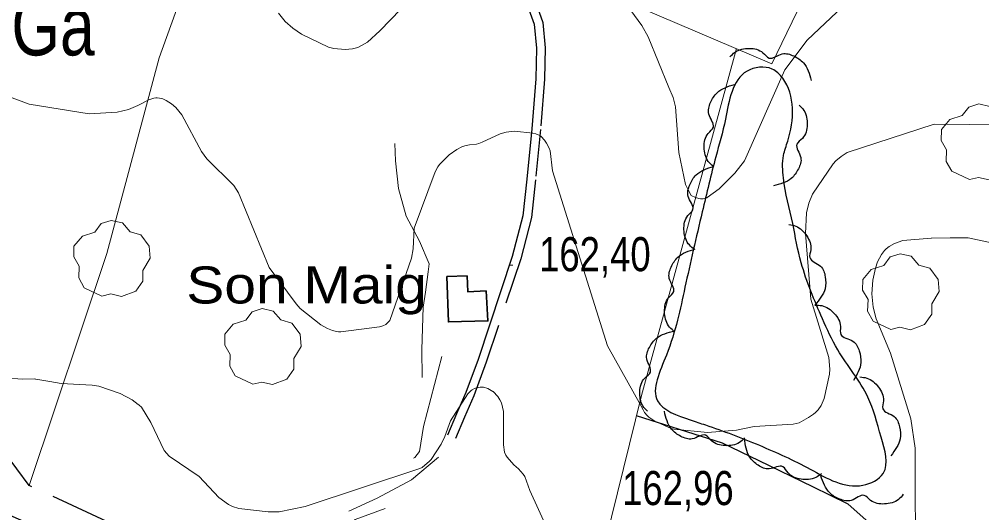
# Model space of a CAD drawing. Extents: x 483840 to 488445, y 4386047 to 4389027.
# Drawn here: x 484357.8 to 484604.8, y 4386593.6 to 4386720.2 of the extents above; entities that cross this region are included whole.
import ezdxf
from ezdxf.enums import TextEntityAlignment as Align

# ---------------------------------------------------------------- set-up
doc = ezdxf.new("R2010")
doc.units = 0
doc.header["$LTSCALE"] = 4
doc.linetypes.add('LONG_DASHED', pattern=[7.5, 6, -1.5])
doc.linetypes.add('MEDIUM_DASHED', pattern=[4.5, 3, -1.5])
for name, color, linetype, lineweight in [('25', 7, 'LONG_DASHED', 25), ('27', 7, 'Continuous', 25), ('29', 7, 'Continuous', 13), ('38', 7, 'Continuous', 25), ('47', 7, 'Continuous', 35), ('51', 7, 'Continuous', 13), ('7', 7, 'Continuous', 13), ('9', 7, 'Continuous', 13)]:
    doc.layers.add(name, color=color, linetype=linetype, lineweight=lineweight)
doc.layers.add('31', color=7, linetype='Continuous')
doc.layers.add('5', color=7, linetype='Continuous')

msp = doc.modelspace()

# ---------------------------------------------------------------- linework, layer by layer
at = {"layer": '25'}
for points in [[(484360.41, 4386600.63), (484354.02, 4386609.13), (484342.83, 4386622.33), (484338.08, 4386628.43), (484332.17, 4386636.95), (484328.3, 4386644.98), (484318.53, 4386649.68), (484308.26, 4386654.85)], [(484625.09, 4386565.41), (484619.55, 4386565.24), (484606.23, 4386564.53), (484601.69, 4386564.69), (484597.73, 4386565.92), (484588.84, 4386577.12), (484578.87, 4386588.38), (484570.49, 4386595.81), (484561.42, 4386600.29), (484547.69, 4386606.96), (484538.24, 4386611.5), (484516.24, 4386618.5)], [(484502.07, 4386561.29), (484498.4, 4386548.69), (484496.9, 4386545.14), (484493.33, 4386545.09), (484491.54, 4386545.96), (484488.97, 4386547.31), (484486.16, 4386546.59), (484479.53, 4386549.16), (484472.38, 4386552.84), (484468.67, 4386554.43), (484462.27, 4386557.73), (484455.18, 4386561.19), (484448, 4386562.42), (484443.71, 4386561.42), (484440.31, 4386560.77), (484431.57, 4386564.01), (484408.49, 4386578.31), (484399.65, 4386582.16), (484388.31, 4386587.7), (484360.41, 4386600.63)]]:
    msp.add_lwpolyline(points, dxfattribs=at)
at = {"layer": '27'}
for points in [[(484540.19, 4386710.56), (484541.48, 4386711.78), (484545.15, 4386712.74), (484548.66, 4386711.61), (484550.21, 4386710.26), (484553.6, 4386711.33), (484556.53, 4386710.79), (484559.01, 4386709.06), (484561.03, 4386704.53)], [(484556.32, 4386667.82), (484558.47, 4386657.74), (484563.92, 4386643.39), (484567.83, 4386635.44), (484575.57, 4386623.28), (484578.97, 4386613.01), (484579.51, 4386603.72), (484574.31, 4386600.68), (484560.8, 4386604.79), (484547.72, 4386610.93), (484533.87, 4386616.16), (484529.98, 4386617.43), (484521.57, 4386622.34), (484523.87, 4386634.06), (484528.64, 4386651.45), (484533.07, 4386670.79), (484536.55, 4386684.93), (484539.03, 4386694.61), (484544.56, 4386706.89), (484551.02, 4386707.43), (484553.72, 4386705.12), (484555.02, 4386688.98), (484553.92, 4386685.29), (484553.91, 4386679.51), (484556.32, 4386667.82)], [(484535.89, 4386682.49), (484534.63, 4386683.75), (484533.57, 4386687.39), (484534.61, 4386690.94), (484535.92, 4386692.52), (484534.75, 4386695.88), (484535.21, 4386698.83), (484536.87, 4386701.35), (484541.34, 4386703.5)], [(484557.95, 4386698.16), (484559.14, 4386696.84), (484559.99, 4386693.15), (484558.77, 4386689.66), (484557.37, 4386688.16), (484558.35, 4386684.74), (484557.73, 4386681.82), (484555.92, 4386679.39), (484551.34, 4386677.5)], [(484109.46, 4386593.06), (484150.94, 4386626.49), (484199.73, 4386650.7), (484203.95, 4386655.31), (484208.18, 4386661.85), (484210.1, 4386669.53), (484207.03, 4386691.82), (484208.56, 4386694.9), (484211.64, 4386696.82), (484215.48, 4386696.43), (484273.86, 4386668), (484283.08, 4386663), (484285.77, 4386658), (484291.92, 4386647.24), (484300.75, 4386636.1), (484310.35, 4386633.02), (484326.87, 4386627.64), (484334.94, 4386616.12), (484338.78, 4386603.82), (484350.3, 4386595.36), (484426.74, 4386553.47), (484429.82, 4386547.71), (484429.82, 4386545.79), (484429.82, 4386540.02), (484422.52, 4386535.03), (484386.41, 4386496.98), (484386.03, 4386493.91), (484387.56, 4386490.45), (484397.55, 4386477), (484431.35, 4386465.85), (484447.87, 4386459.7), (484460.55, 4386449.71), (484465.92, 4386445.87)], [(484530.77, 4386661.41), (484529.5, 4386662.64), (484528.39, 4386666.27), (484529.38, 4386669.83), (484530.66, 4386671.43), (484529.45, 4386674.77), (484529.87, 4386677.73), (484531.5, 4386680.27), (484535.95, 4386682.48)], [(484555.32, 4386667.55), (484557.05, 4386667.16), (484559.89, 4386664.65), (484560.92, 4386661.11), (484560.66, 4386659.07), (484563.44, 4386656.86), (484564.63, 4386654.12), (484564.58, 4386651.1), (484561.95, 4386646.89)], [(484525.68, 4386640.32), (484524.43, 4386641.58), (484523.4, 4386645.23), (484524.45, 4386648.76), (484525.77, 4386650.34), (484524.62, 4386653.71), (484525.1, 4386656.65), (484526.78, 4386659.17), (484531.26, 4386661.29)], [(484561.96, 4386646.86), (484563.74, 4386646.76), (484566.95, 4386644.74), (484568.54, 4386641.41), (484568.62, 4386639.36), (484571.72, 4386637.63), (484573.34, 4386635.12), (484573.78, 4386632.13), (484571.87, 4386627.55)], [(484519.02, 4386619.67), (484517.86, 4386621.01), (484517.06, 4386624.72), (484518.34, 4386628.18), (484519.76, 4386629.66), (484518.84, 4386633.1), (484519.5, 4386636.01), (484521.35, 4386638.41), (484525.96, 4386640.23)], [(484573.54, 4386628.45), (484575.29, 4386628.17), (484578.29, 4386625.85), (484579.54, 4386622.37), (484579.41, 4386620.32), (484582.32, 4386618.29), (484583.69, 4386615.63), (484583.82, 4386612.61), (484581.47, 4386608.25)], [(484543.94, 4386612.82), (484542.61, 4386611.65), (484538.9, 4386610.84), (484535.43, 4386612.1), (484533.94, 4386613.51), (484530.51, 4386612.57), (484527.6, 4386613.22), (484525.19, 4386615.05), (484523.35, 4386619.66)], [(484563.65, 4386603.66), (484562.19, 4386602.65), (484558.42, 4386602.23), (484555.11, 4386603.87), (484553.78, 4386605.43), (484550.27, 4386604.86), (484547.44, 4386605.82), (484545.25, 4386607.9), (484543.91, 4386612.68)], [(484584.65, 4386598.35), (484583.43, 4386597.05), (484579.83, 4386595.88), (484576.25, 4386596.8), (484574.63, 4386598.06), (484571.31, 4386596.79), (484568.34, 4386597.15), (484565.77, 4386598.73), (484563.48, 4386603.13)]]:
    msp.add_spline(points, degree=3, dxfattribs=at)
at = {"layer": '29'}
for points in [[(484601.62, 4386679.1), (484597.08, 4386681.22), (484595.67, 4386683.76), (484595.77, 4386686.74), (484594.4, 4386689.15), (484594.44, 4386691.9), (484596.6, 4386694.5), (484599.79, 4386695.5), (484601.44, 4386697.69), (484604.01, 4386698.52), (484606.87, 4386697.87), (484608.82, 4386695.6), (484611.63, 4386694.78), (484613.76, 4386691.93), (484614, 4386688.8), (484612.12, 4386685.65), (484612.12, 4386682.97), (484610.3, 4386680.36), (484606.68, 4386679.02), (484603.91, 4386679.65)], [(484379.06, 4386649.2), (484374.52, 4386651.32), (484373.11, 4386653.86), (484373.21, 4386656.84), (484371.84, 4386659.25), (484371.88, 4386662), (484374.04, 4386664.6), (484377.23, 4386665.6), (484378.88, 4386667.79), (484381.45, 4386668.62), (484384.31, 4386667.97), (484386.26, 4386665.7), (484389.07, 4386664.88), (484391.2, 4386662.03), (484391.44, 4386658.9), (484389.56, 4386655.75), (484389.56, 4386653.07), (484387.74, 4386650.46), (484384.12, 4386649.12), (484381.35, 4386649.75)], [(484581.45, 4386640.66), (484576.91, 4386642.78), (484575.5, 4386645.32), (484575.6, 4386648.3), (484574.23, 4386650.71), (484574.27, 4386653.46), (484576.43, 4386656.06), (484579.62, 4386657.06), (484581.27, 4386659.25), (484583.84, 4386660.08), (484586.7, 4386659.43), (484588.65, 4386657.16), (484591.46, 4386656.34), (484593.59, 4386653.49), (484593.83, 4386650.36), (484591.95, 4386647.21), (484591.95, 4386644.53), (484590.13, 4386641.92), (484586.51, 4386640.58), (484583.74, 4386641.21)], [(484417.78, 4386626.6), (484413.24, 4386628.72), (484411.83, 4386631.26), (484411.93, 4386634.24), (484410.56, 4386636.65), (484410.6, 4386639.4), (484412.76, 4386642), (484415.95, 4386643), (484417.6, 4386645.19), (484420.17, 4386646.02), (484423.03, 4386645.37), (484424.98, 4386643.1), (484427.79, 4386642.28), (484429.92, 4386639.43), (484430.16, 4386636.3), (484428.28, 4386633.15), (484428.28, 4386630.47), (484426.46, 4386627.86), (484422.84, 4386626.52), (484420.07, 4386627.15)]]:
    msp.add_lwpolyline(points, close=True, dxfattribs=at)
at = {"layer": '38'}
msp.add_lwpolyline([(484503.94, 4386804.39), (484500.14, 4386794.1), (484495.04, 4386779.48), (484492.44, 4386773.52), (484487.95, 4386764.75), (484483.27, 4386753.75), (484479.76, 4386743.29), (484479.64, 4386739.82), (484480.35, 4386735.84), (484482.04, 4386732.77), (484488.27, 4386723.67), (484489.97, 4386718.91), (484490.51, 4386712.77), (484490.38, 4386704.96), (484489.34, 4386692.14), (484488.04, 4386679.23), (484487.01, 4386669.77), (484484.32, 4386659.38), (484475.55, 4386632.97), (484472.4, 4386624.43), (484469.99, 4386619), (484467.68, 4386613.52)], dxfattribs=at)
at = {"layer": '38', "linetype": 'MEDIUM_DASHED'}
msp.add_lwpolyline([(484506.1, 4386803.76), (484502.25, 4386793.34), (484497.14, 4386778.66), (484494.47, 4386772.56), (484489.99, 4386763.8), (484485.37, 4386752.95), (484481.99, 4386742.89), (484481.89, 4386739.98), (484482.5, 4386736.6), (484483.96, 4386733.94), (484490.29, 4386724.69), (484492.18, 4386719.4), (484492.76, 4386712.85), (484492.63, 4386704.85), (484491.58, 4386691.94), (484490.27, 4386678.99), (484489.23, 4386669.37), (484486.49, 4386658.74), (484477.67, 4386632.22), (484474.48, 4386623.58), (484472.05, 4386618.11), (484469.75, 4386612.65)], dxfattribs=at)
at = {"layer": '47'}
msp.add_lwpolyline([(484467.51, 4386654.23), (484467.94, 4386642.56), (484478.07, 4386642.84), (484477.61, 4386650.54), (484472.95, 4386650.27), (484472.72, 4386654.36)], close=True, dxfattribs=at)
at = {"layer": '51'}
for points in [[(484426.66, 4386813.96), (484413.06, 4386763.95), (484393.76, 4386710.28), (484380.34, 4386660.15), (484360.41, 4386600.63)], [(484584.64, 4386778.48), (484550.96, 4386708.8), (484483.24, 4386737.68)], [(484541.9, 4386712.67), (484517.51, 4386623.68), (484502.07, 4386561.29)], [(484461.19, 4386628.31), (484461.14, 4386635.54), (484461.5, 4386646.36), (484462.08, 4386650.24), (484462.77, 4386655.4), (484463, 4386657.47), (484460.57, 4386663.28), (484457.09, 4386669.71), (484455.15, 4386676.76), (484454.4, 4386683.87), (484454.18, 4386688.31)], [(484466.25, 4386633.69), (484461.56, 4386615.74), (484460.56, 4386609.35), (484459.34, 4386607.79), (484458.97, 4386607.61)], [(484442.38, 4386594.04), (484449.67, 4386597.34), (484458.5, 4386602.06), (484465.42, 4386607.84)], [(484451.74, 4386594.71), (484444.01, 4386591.92), (484439.66, 4386587.8), (484434.99, 4386581.93), (484433.06, 4386579.22)]]:
    msp.add_lwpolyline(points, dxfattribs=at)
at = {"layer": '7'}
msp.add_line((484483.49, 4386657.16), (484484.49, 4386657.16), dxfattribs=at)
at = {"layer": '9'}
for points in [[(484455.72, 4386722.83), (484450.36, 4386717.24), (484447.18, 4386714.37), (484444.86, 4386713.03), (484444.72, 4386712.97), (484443.37, 4386712.65), (484441.49, 4386712.46), (484438.57, 4386712.68), (484437.2, 4386713.08), (484430.29, 4386716.41), (484428.03, 4386717.89), (484426.06, 4386719.63), (484424.4, 4386721.8)], [(484543.9, 4386683.87), (484541.4, 4386680.72), (484537.4, 4386676.72), (484534.35, 4386674.48), (484534.25, 4386674.39), (484534.1, 4386674.32), (484533.33, 4386674.18), (484532.61, 4386674.16), (484532.18, 4386674.24), (484531.37, 4386674.51), (484530.27, 4386675.04), (484529.26, 4386676.78), (484528.82, 4386677.81), (484527.08, 4386686.03), (484526.2, 4386697.77), (484525.62, 4386700.15), (484524.49, 4386702.73), (484519.22, 4386715.7), (484517.61, 4386718.65), (484514.73, 4386722.42)], [(484569.15, 4386723.49), (484560, 4386714.85), (484554.25, 4386707.23), (484543.9, 4386683.87)], [(484356.07, 4386700.09), (484360.43, 4386698.46), (484375.82, 4386695.94), (484382.94, 4386696.37), (484385.85, 4386697.03), (484388.27, 4386698.06), (484391.06, 4386699.54), (484391.85, 4386699.83), (484392.36, 4386699.97), (484392.9, 4386700.04), (484393.23, 4386700.04), (484393.87, 4386699.98), (484394.72, 4386699.76), (484395.54, 4386699.39), (484396.9, 4386698.51), (484397.98, 4386697.55), (484399.52, 4386695.68), (484404.62, 4386686.26), (484405.97, 4386684.44), (484412.86, 4386677.56), (484414.1, 4386675.69), (484421.93, 4386656.57), (484428.85, 4386647.2), (484429.93, 4386646), (484435.23, 4386641.86), (484436.92, 4386640.87), (484438.2, 4386640.35), (484438.92, 4386640.17), (484439.79, 4386640.05), (484440.35, 4386640.05), (484450.25, 4386641.29)], [(484450.25, 4386641.29), (484451.16, 4386641.53), (484451.89, 4386641.91), (484452.27, 4386642.22), (484452.9, 4386642.94), (484458.49, 4386658.9), (484458.92, 4386661.28), (484459.15, 4386666.61), (484464.53, 4386681.03), (484465.25, 4386682.32), (484465.68, 4386682.93), (484468.17, 4386685.4), (484470.07, 4386686.77), (484471.4, 4386687.47), (484472.19, 4386687.76), (484473.37, 4386688.02), (484475.14, 4386688.21), (484475.72, 4386688.36), (484476.58, 4386688.71), (484481.21, 4386690.85), (484482.79, 4386691.27), (484484.87, 4386691.49), (484489.57, 4386690.95), (484490.4, 4386690.78), (484491.01, 4386690.58), (484491.29, 4386690.44), (484491.73, 4386690.15), (484492.64, 4386689.19), (484493.15, 4386688.44), (484493.82, 4386687.11), (484494.03, 4386686.44), (484494.67, 4386681.31), (484508.78, 4386636.48), (484517.36, 4386621.17), (484517.9, 4386620), (484518.29, 4386619.37), (484518.93, 4386618.55), (484519.38, 4386618.14), (484520.91, 4386617.13), (484525.1, 4386615.27), (484525.76, 4386615.06), (484534.38, 4386614.25), (484541.86, 4386614.82), (484546.37, 4386615.75), (484556.41, 4386616.37), (484557.9, 4386616.73), (484560.35, 4386618.04), (484561.62, 4386618.9), (484562.16, 4386619.35), (484562.79, 4386620.02), (484563.57, 4386621.14), (484564.38, 4386622.94), (484565.72, 4386629.2), (484565.82, 4386630.42), (484565.56, 4386633.47), (484560.96, 4386648.4), (484559.56, 4386665.23), (484559.84, 4386670.52), (484560.41, 4386673.02), (484561.33, 4386675.35), (484566.67, 4386683.13), (484567.37, 4386683.93), (484568.69, 4386685.04), (484570.23, 4386686.01), (484592.56, 4386693.31), (484619.64, 4386693.04)], [(484587.78, 4386577.36), (484587.73, 4386610.21), (484586.55, 4386617.69), (484581.39, 4386634.53), (484577.66, 4386643.4), (484576.89, 4386646.39), (484576.62, 4386649.77), (484576.86, 4386653.28), (484577.49, 4386656.4), (484578.06, 4386658.01), (484579.06, 4386659.83), (484579.83, 4386660.86), (484580.28, 4386661.33), (484581.01, 4386661.9), (484582.36, 4386662.67), (484584.51, 4386663.44), (484591.84, 4386664.05), (484591.87, 4386664.06), (484596.69, 4386664.12), (484601.27, 4386664.14), (484612.06, 4386661.81)], [(484338.47, 4386629.29), (484358.75, 4386627.92), (484361.78, 4386627.95), (484362.01, 4386627.93), (484362.05, 4386627.9), (484362.06, 4386627.89), (484362.06, 4386627.91), (484362.06, 4386627.93), (484365.65, 4386627.27), (484368.6, 4386626.75), (484376.56, 4386626.33), (484378.23, 4386626.06), (484383.72, 4386624.23), (484386.8, 4386622.61), (484388.35, 4386621.43), (484388.51, 4386621.33), (484388.65, 4386621.23), (484389.17, 4386620.67), (484391.58, 4386616.8), (484395.05, 4386609.6), (484395.06, 4386609.59), (484396.29, 4386608.15), (484404.02, 4386602.9), (484409.08, 4386597.53), (484411.52, 4386595.75), (484412.57, 4386595.22), (484414.19, 4386594.69), (484421.73, 4386593.82), (484424.55, 4386593.89), (484431.2, 4386595.25), (484460.64, 4386604.95), (484461.23, 4386605.25), (484463.08, 4386606.83), (484463.54, 4386607.32)], [(484463.54, 4386607.32), (484466.06, 4386611.25), (484467.02, 4386613.2), (484468.52, 4386617.23), (484472.95, 4386624.14), (484473.43, 4386624.68), (484473.78, 4386625), (484474.05, 4386625.17), (484474.64, 4386625.46), (484475.44, 4386625.75), (484475.59, 4386625.78), (484476.12, 4386625.85), (484476.74, 4386625.84), (484476.97, 4386625.8), (484478.04, 4386625.51), (484479.38, 4386624.74), (484479.4, 4386624.73), (484480.59, 4386623.45), (484481.18, 4386622.57), (484481.53, 4386621.8), (484482.12, 4386619.6), (484482.12, 4386611.06), (484482.37, 4386609.15), (484482.7, 4386608.43), (484483.02, 4386607.84), (484484.7, 4386605.94), (484485.97, 4386604.85), (484487.13, 4386603.56), (484487.55, 4386602.9), (484488.8, 4386599.35), (484493.7, 4386588.66)]]:
    msp.add_lwpolyline(points, dxfattribs=at)

# ---------------------------------------------------------------- texts
at = {"layer": '31', "width": 0.8}
msp.add_text('Ga', height=15, dxfattribs=at).set_placement((484366.52, 4386710.94), align=Align.CENTER)
at = {"layer": '5', "width": 1.15}
msp.add_text('Son Maig', height=9.5, dxfattribs=at).set_placement((484400.71, 4386647.3))
at = {"layer": '7', "width": 0.8}
for s, p in [('162,40', (484491.21, 4386655.58)), ('162,96', (484512.51, 4386595.59))]:
    msp.add_text(s, height=8.75, dxfattribs=at).set_placement(p)

doc.saveas('drawing.dxf')
